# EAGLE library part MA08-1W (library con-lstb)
PIN HEADER
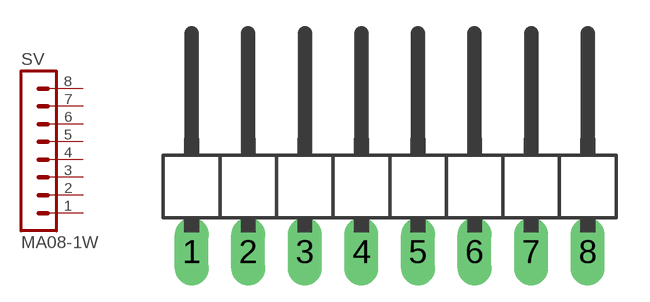
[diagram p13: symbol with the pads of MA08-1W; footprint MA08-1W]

Designator prefix SV

## MA08-1W (OC_FARNELL: unknown; OC_NEWARK: unknown)  [MA08-1W]
1  1  pas
2  2  pas
3  3  pas
4  4  pas
5  5  pas
6  6  pas
7  7  pas
8  8  pas

## Footprint MA08-1W (pad centres in mm)
PIN HEADER
drill 1.016 long: 1 -8.89,0; 2 -6.35,0; 3 -3.81,0; 4 -1.27,0; 5 1.27,0; 6 3.81,0; 7 6.35,0; 8 8.89,0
